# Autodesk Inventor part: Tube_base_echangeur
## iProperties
Shininess: 64.0
Length Units: 11269
Angle Units: 11279
Time Units: 11290
Mass Units: 11283
Length Display Precision: 3
Angle Display Precision: 2
Compacted: True
Part Number: Tube_base_echangeur
Document SubType Name: Modeling
Created: 2008-02
Material: Acier inoxydable, austénitique
Designer: Pascal
Density: 8.03 g/cm^3
Density: 0.0
Volumn: 0.0
Area: 0.0
PropertySet Name: Model Information
Control State: 0
Master: False
Checked Out: False
MATIERE_PIECE: X2CrNi 18-11
OBSERVATIONS: Øext 610 ep 6
DESIGNATION: Tube base corps
Author: Pascal
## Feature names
1. Extrusion1
2. Extrusion2
3. Extrusion3
